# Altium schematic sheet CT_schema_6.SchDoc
size 277 x 170 mm
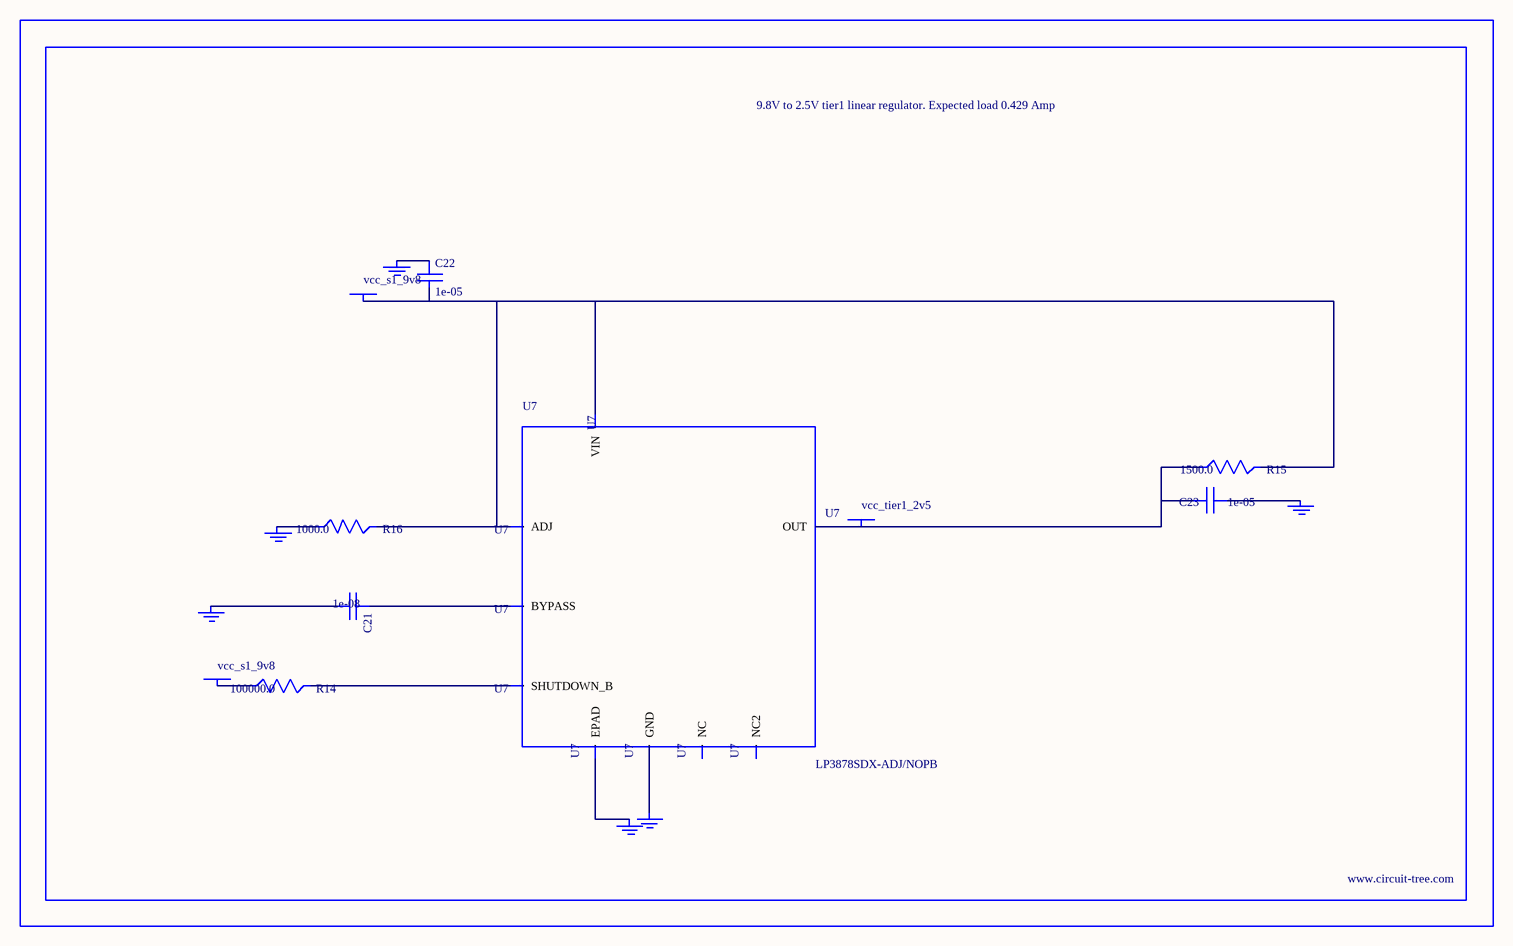
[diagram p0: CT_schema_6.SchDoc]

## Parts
BORDER5  (no value)
C21  1e-08  [C0402]
C22  1e-05  [C1206]
C23  1e-05  [C1210]
GND_INSTANCE_5_0  (no value)
GND_INSTANCE_5_1  (no value)
GND_INSTANCE_5_2  (no value)
GND_INSTANCE_5_3  (no value)
GND_INSTANCE_5_4  (no value)
GND_INSTANCE_5_5  (no value)
POWER_INSTANCE_5_0  vcc_s1_9v8
POWER_INSTANCE_5_1  vcc_s1_9v8
POWER_INSTANCE_5_2  vcc_tier1_2v5
R14  100000.0  [R0603]
R15  1500.0  [R0603]
R16  1000.0  [R0603]
U7  LP3878SDX-ADJ/NOPB  [WSON-8]

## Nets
NetC21_1: C21.1 U7.1(BYPASS)
NetC21_2: C21.2 GND_INSTANCE_5_0.0(GND)
NetC22_1: C22.1 GND_INSTANCE_5_1.0(GND)
NetC22_2: C22.2 POWER_INSTANCE_5_0.0(PWR) R15.2 R16.2 U7.4(VIN) U7.6(ADJ)
NetC23_1: C23.1 GND_INSTANCE_5_2.0(GND)
NetC23_2: C23.2 POWER_INSTANCE_5_2.0(PWR) R15.1 U7.5(OUT)
NetGND_INSTANCE_5_3_0: GND_INSTANCE_5_3.0(GND) R16.1
NetGND_INSTANCE_5_4_0: GND_INSTANCE_5_4.0(GND) U7.PAD(EPAD)
NetGND_INSTANCE_5_5_0: GND_INSTANCE_5_5.0(GND) U7.3(GND)
NetPOWER_INSTANCE_5_1_0: POWER_INSTANCE_5_1.0(PWR) R14.1
NetR14_2: R14.2 U7.8(SHUTDOWN_B)

Not connected (* = marked no-connect by the designer): U7 2(NC) 7(NC2)

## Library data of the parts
BORDER5 = BORDER_PAGE5
C21 = C0402C103K3RAC
C22 = C1206C106K3RACTU
C23 = GRM32DR61E106MA12L
GND_INSTANCE_5_0-GND_INSTANCE_5_5 = GND
POWER_INSTANCE_5_0-POWER_INSTANCE_5_2 = PWR
R14 = RC0603JR-07100KL
R15 = RC0603JR-071K5L
R16 = RC0603JR-071KL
